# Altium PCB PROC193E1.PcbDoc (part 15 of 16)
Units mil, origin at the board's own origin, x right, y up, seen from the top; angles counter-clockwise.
Board outline 7700 x 2300 mil, 6 copper layers (Top Layer, GND 1, SIG 1, PWR, GND 2, Bottom Layer), stack 60.98 mil thick; 946 components, 667 nets, 9401 pads, 1730 vias.
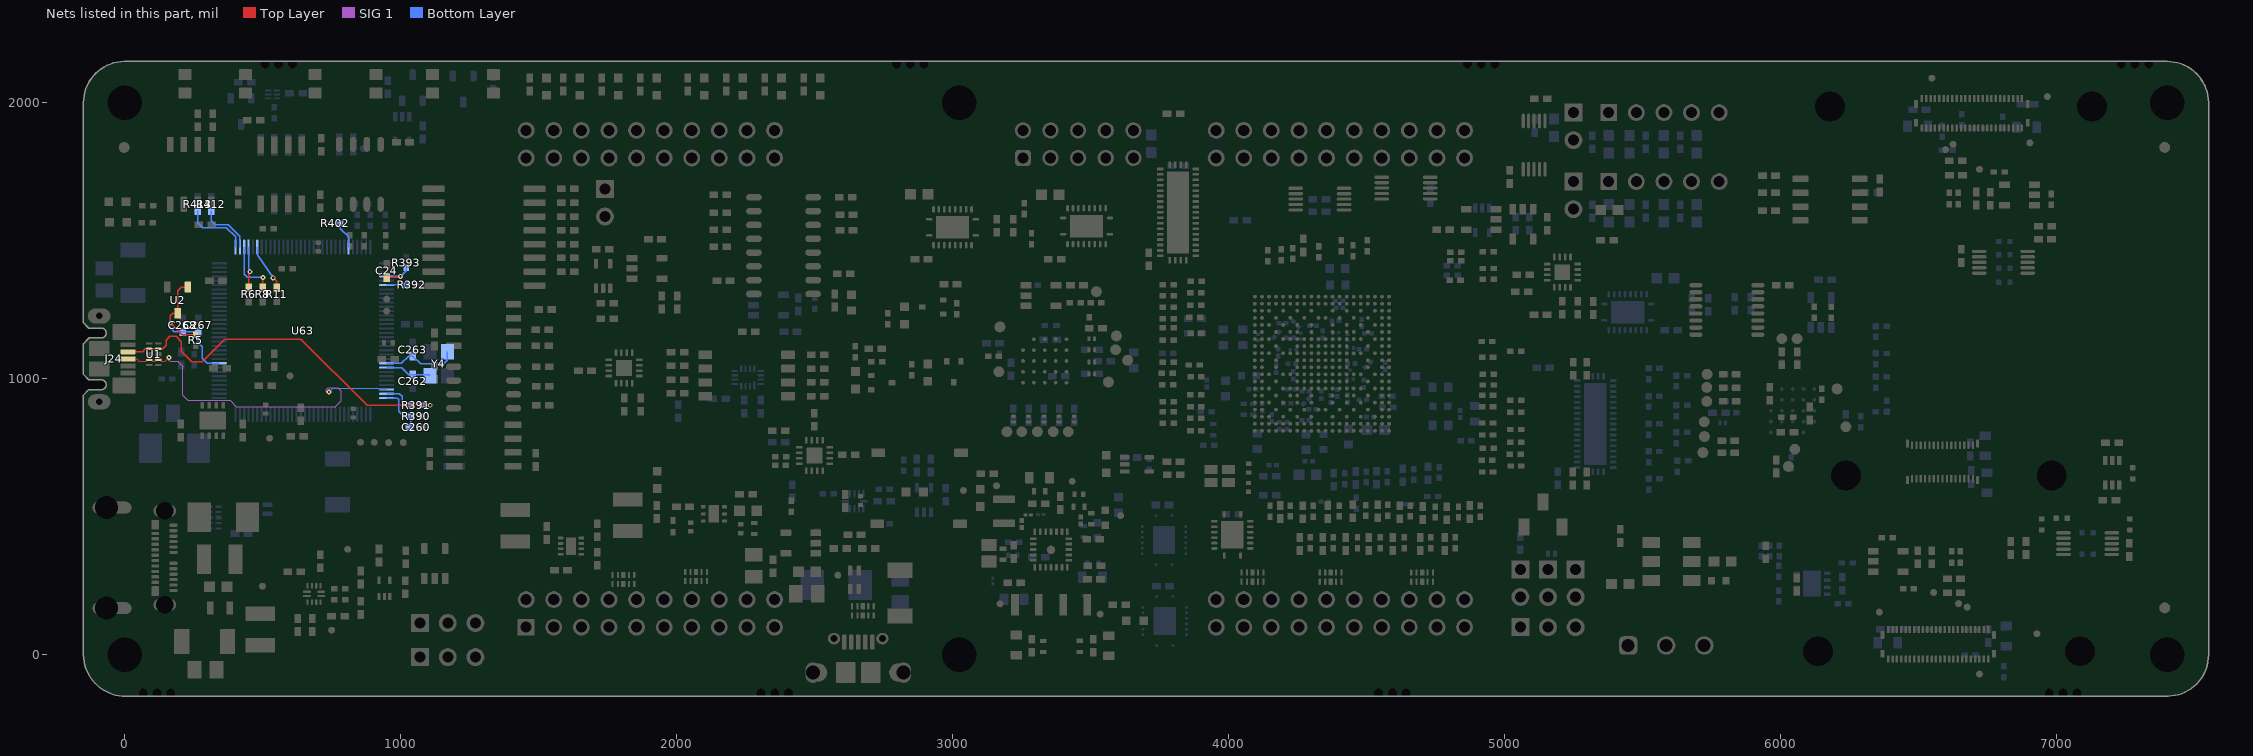
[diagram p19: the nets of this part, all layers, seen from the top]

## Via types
v1: diameter 18, hole 8, Top Layer to Bottom Layer, tented both sides, 1710 vias
v2: diameter 18, hole 8, Top Layer to Bottom Layer, tented top, 12 vias
v3: diameter 23.62, hole 11.81, Top Layer to Bottom Layer, tented both sides, 8 vias

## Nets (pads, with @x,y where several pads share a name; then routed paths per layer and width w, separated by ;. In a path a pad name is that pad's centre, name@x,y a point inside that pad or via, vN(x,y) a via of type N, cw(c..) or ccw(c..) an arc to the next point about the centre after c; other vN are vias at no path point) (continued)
XDSET_1_D_P: J24.3 U1.2 U1.9 U63.94 | length 1271.6
  Top Layer w4.2: J24.3@11.81,1072.19 42.99,1072.19 51.19,1063.99 76.14,1063.99 81.38,1069.23 U1.9@88.56,1069.23 95.75,1069.23 100.99,1063.99 109.01,1063.99 114.25,1069.23 U1.2@121.44,1069.23 128.62,1069.23 128.62,1068.29 132.92,1063.99 146.6,1063.99 v1(160,1077.39)
  SIG 1 w4: v1(160,1077.39) 160,1068.11 165,1063.11 192.24,1063.11 209.9,1045.45 209.9,940.01 228.42,921.48 381.95,921.48 404.66,898.78 762.96,898.78 785,920.82 785,954.8 772.28,967.52 736.99,967.52 729.55,960.08 729.55,955.61 733.52,951.65 v1(740,951.65)
  Bottom Layer w4.2: v1(740,951.65) 753.4,965.05 917.83,965.05 921.1,961.77 U63.94@948.65,961.77
XDSET_1_ID: J24.4 R391.1 U1.4 U1.7 | length 1351.3
  Top Layer w5.3: J24.4@11.81,1097.78 64.17,1097.78 75,1108.6 U1.7@88.56,1108.6 U1.4@121.44,1108.6 136.73,1108.6 149.79,1121.67 149.79,1140.24 163.21,1153.65 185.77,1153.65 205.14,1134.28 205.14,1099.59 243.04,1061.69 280.18,1061.69 362.27,1143.79 638.14,1143.79 877.71,904.21 v1(1106.33,904.21)
  Bottom Layer w5.3: R391.1@1075.19,904.21 v1(1106.33,904.21)
XDSET_1_ID_R: R391.2 U63.95 | length 117.4
  Bottom Layer w5.3: U63.95@948.65,946.02 995.21,946.02 1005,936.23 1005,914.12 1014.91,904.21 R391.2@1035.82,904.21
XDSET_NRST: R392.1 U63.70 | length 72.4
  Bottom Layer w5.3: U63.70@948.65,1339.72 949.32,1340.39 R392.1@1020.82,1340.39
XDSET_OSC0: C263.2 U63.88 Y4.1 | length 278.7
  Bottom Layer w5.3: U63.88@948.65,1056.26 1001.79,1056.26 1028.04,1082.51 C263.2@1042.72,1082.51 1071.4,1053.83 1155.21,1053.83 1168.63,1067.24 Y4.1@1168.63,1097.63
XDSET_OSC1: C262.2 U63.89 Y4.3 | length 169.2
  Bottom Layer w5.3: U63.89@948.65,1040.51 1002.75,1040.51 1028.31,1014.95 C262.2@1042.72,1014.95 1101.7,1014.95 Y4.3@1105.64,1011.01
XDSET_RBIAS: R402.2 U63.59 | length 98.3
  Bottom Layer w5.3: R402.2@781.47,1563.62 781.47,1543.52 810.85,1514.13 U63.59@810.85,1477.52
XDSET_TCK: R8.2 U63.35 | length 209.9
  Top Layer w5.3: R8.2@500,1329.36 500,1366.5 v1(500.77,1367.28)
  Bottom Layer w5.3: U63.35@432.9,1477.52 432.9,1378.38 444,1367.28 v1(500.77,1367.28)
XDSET_TDI: R11.2 U63.38 | length 170
  Top Layer w5.3: v1(537.79,1365.91) 549.89,1353.81 R11.2@549.89,1329.99
  Bottom Layer w5.3: U63.38@480.15,1477.52 480.15,1453.9 481.91,1448.1 v1(537.79,1365.91)
XDSET_TMS: R6.2 U63.36 | length 152.5
  Top Layer w5.3: R6.2@448.79,1329.36 448.79,1379.32 453.93,1384.46 v1(453.93,1387.9)
  Bottom Layer w5.3: U63.36@448.65,1477.52 448.65,1396.62 453.93,1391.34 v1(453.93,1387.9)
XDSET_UARTA_RX: R413.2 U63.33 | length 238.9
  Bottom Layer w5.3: R413.2@264.01,1609.62 264.01,1566.16 283.33,1546.84 368.48,1546.84 401.41,1513.91 U63.33@401.41,1477.52
XDSET_UARTA_TX: R412.2 U63.34 | length 202.3
  Bottom Layer w5.3: R412.2@314.01,1609.62 314.01,1572.04 327.4,1558.65 374.37,1558.65 417.15,1515.86 U63.34@417.15,1477.52
XDSET_VBAT: C24.1 R393.1 U63.68 | length 141.4
  Top Layer w5.3: C24.1@948.65,1367.28 995.1,1367.28 v1(999.04,1371.22)
  Bottom Layer w5.3: U63.68@948.65,1371.22 v1(999.04,1371.22) 1020,1392.18 R393.1@1020,1401.56
XDSET_VREFA: C267.2 C268.2 R5.1 U2.1 U2.3 U63.9 | length 587.1
  Top Layer w5.3: U2.1@228.9,1332 203.89,1332 191.5,1319.61 U2.3@191.5,1237.51 173.18,1237.51 165,1229.33 v1(165,1203.44) 208.88,1159.56 R5.1@257.13,1159.56
  Bottom Layer w5.3: v1(165,1203.44) 165,1185.04 179.89,1170.15 C268.2@210.82,1170.15 C267.2@265.82,1170.15 265.82,1131.18 280.11,1116.89 280.11,1075.03 298.89,1056.26 U63.9@342.35,1056.26
XDSUSB0VBUS: C260.2 R390.1 U63.96 | length 179.6
  Bottom Layer w5.3: U63.96@948.65,930.28 987.32,930.28 992.6,925 992.6,882.15 1010.53,864.22 R390.1@1035.82,864.22 C260.2@1035.82,824.22
pads on no net: 1. 2. 3. 4. 5. 7. 8. 9. 10. 11. D17.1S D17.2S Designator1. Designator2. Designator3. Designator4. Designator5. Designator6. Designator7. Designator8. Designator9. Designator10. Designator11. Designator12. Designator13. Designator14. Designator15. Designator16. Designator17. Designator18. Designator19. Designator20. Designator21. Designator22. FID1.1 FID1_1.1 FID1_1_1.1 FID1_1_2.1 FID1_1_3.1 FID2.1 FID3.1 FID4.1 FID4_1.1 FID4_1_1.1 FID4_1_2.1 FID4_1_3.1 FID5.1 FID6.1 J22.24 J22.25 J22.26 J22.27 J22.28 J22.29 J22.30 J25.A2 J25.A3 J25.A8 J25.A10 J25.A11 J25.B2 J25.B3 J25.B8 J25.B10 J25.B11 LBL1.0 SH-J1.0 SH-J2.0 SH-J3.0 SH-J4.0 SH-J5.0 SH-J6.0 SH-J7.0 SH-J8.0 U1.3@121.44,1088.92 U1.5 U1.6 U1.8@88.56,1088.92 U4.7 U4.9@293.89,848.32 U4.9@343.49,848.32 U14.0 U15.1 U16.7 U16.8 U16.9 U16.10 U16.17@1809.13,1039.54 U17.3@1806.54,256.9 U17.8@1806.54,289.78 U19.3@2069.81,267.45 U19.8@2069.81,300.32 U20.5 U20.7@2134.1,492.72 U20.7@2134.1,528.15 U23.17@2498.69,722.15 U24.3@2674,142.95 U24.5 U24.6 U24.8@2674,175.83 U26.A2 U26.A3 U26.B1 U26.B5 U26.C5 U29.6 U29.15 U31.16 U31.18 U31.19 U33.3@4085.92,264.9 U33.8@4085.92,297.78 U34.U17 U36.3@4369.09,297.78 U36.8@4369.09,264.9 U38.3@4700.31,297.78 U38.8@4700.31,264.9 U42.17@5208.52,1386.21 U43.3 U43.12 U43.13 U43.14 U51.A2 U51.A3 U51.B1 U51.B5 U51.C5 U55.1 U56.12 U56.13 U56.14 U59.6 U59.12 U62.1 U63.2 U63.5 U63.6 U63.11 U63.12 U63.13 U63.14 U63.15 U63.18 U63.19 U63.20 U63.21 U63.22 U63.23 U63.24 U63.25 U63.27 U63.29 U63.30 U63.31 U63.32 U63.40 U63.41 U63.44 U63.45 U63.46 U63.53 U63.54 U63.56 U63.57 U63.65 U63.67 U63.83 U63.84 U63.85 U63.86 U63.91 U63.92 U63.102 U63.103 U63.104 U63.105 U63.106 U63.107 U63.108 U63.109 U63.110 U63.111 U63.112 U63.116 U63.117 U63.118 U63.119 U63.120 U63.121 U63.123 U63.124 U63.125 U63.126 U63.127 U63.128 U65.3@306.02,497.27 U65.8@338.89,497.27

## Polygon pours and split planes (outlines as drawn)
GND on Top Layer "NONET_L-01_P-001" (solid, remove dead copper, pour order 435): -15.19,2149.23 7451.59,2149.23 7550,2050.82 7550,-68.99 7468.99,-150 -18.42,-150 -148.4,-20.02 -148.4,2018.56 -18.05,2148.91
GND on Top Layer "GND 1-GND" (solid, remove dead copper, pour order 434): 231.17,592.07 212.36,573.26 212.36,509.24 191.6,488.49 25,488.49 25,221.51 213.11,221.51 307.01,127.6 307.01,-150 7550,-150 7550,2149.99 -150,2150.53 -150,1778.42 1334.22,1778.42 1334.22,592.07
GND_XDS on Top Layer "SIG 1-VDD_XDS3V3" (solid, pour order 410): 40.11,861.16 41,862.05 41,1114.67 96.18,1169.86 96.18,1372.55 -120,1372.55 -120,1699.76 1266.69,1699.76 1266.69,668.8 -130.32,668.8 -130.32,860.97 -130.12,861.16
SHIELD5 on Top Layer "NONET_L-01_P-001" (solid, pour order 355): 2974.79,224.27 2974.79,142.62 2878.87,46.69 2878.87,-123.83 2443.02,-123.83 2443.02,69.26 2458.87,85.11 2586.46,85.11 2586.46,12.74 2591.36,7.84 2718.57,7.84 2721.98,11.25 2721.98,72.03 2735.44,85.49 2735.44,224.27
GND on Top Layer "NONET_L08_P-001" (solid, remove dead copper, pour order 383): 3360.88,304.77 3351.02,304.77 3351.02,306.75 3310.53,347.24 3310.53,425.68 3351.02,466.17 3351.02,485.55 3336.99,499.58 3320.62,515.95 3320.62,674.03 3401.46,674.03 3401.46,555.87 3372.67,555.87 3360.88,544.08 3360.88,435 3370.91,424.96 3383.48,424.96 3390.54,432.02 3390.54,461.18 3449.59,520.23 3449.59,585.56 3466.16,602.13 3564.98,602.13 3579.55,587.55 3579.55,504.92 3566.61,491.98 3435.37,491.98 3401.46,458.06 3401.46,347.32 3360.88,306.75
VSYS_3V3 on Top Layer "TOP_LAYER_VSYS_3V3_P415" (solid, pour order 415): 6777.38,170.53 6777.78,170.92 6777.78,228.15 6723.17,228.15 6712.58,217.56 6712.58,78.37 6713.15,77.8 6751.18,77.23 6777.38,103.43 6777.38,155.63
VSYS_3V3 on Top Layer "NONET_L08_P-001" (solid, remove dead copper, pour order 361): 3443.33,334.07 3469.19,359.93 3505.14,359.93 3505.14,306.43 3500.08,301.36 3413.94,301.36 3410.09,305.22 3410.09,334.07
VSYS_5V0 on Top Layer "NONET_L08_P-001" (solid, remove dead copper, pour order 357): 3303.01,406.57 3273.54,406.57 3263.98,416.13 3166.55,416.13 3099.42,483.25 3055.53,483.25 3055.53,373.17 3233.69,373.17 3240.12,379.6 3254.86,394.34 3303.01,394.34
VUSB_5V0 on Top Layer "Top Layer-VUSB_5V0" (solid, pour order 286): 1222.91,293.21 1222.91,441.28 1589.79,441.28 1589.79,395.68 1561.88,395.68 1534.79,368.6 1534.79,293.21
VSYS_5V0 on Top Layer "NONET_L-01_P-001" (solid, pour order 271): 3216.24,283.34 3227.54,272.05 3227.54,262.84 3227.56,242.34 3276.33,242.34 3322,288.02 3322,326.74 3320.35,328.39 3312.81,328.39 3311.66,327.24 3311.66,306.09 3303.9,298.33 3293.98,298.33 3265.58,326.74 3199.85,326.74 3199.85,283.34
VSYS_3V3 on Top Layer "NONET_L-01_P-001" (solid, remove dead copper, pour order 382): 6547.24,1840.53 6547.24,1921.27 6546.1,1922.41 6523.58,1922.41 6522.44,1921.27 6522.44,1895.04 6514.04,1886.64 6514.04,1840.53
VSYS_5V0 on Top Layer "Top Layer-VSYS_5V0" (solid, pour order 350): 1904.7,511.4 1874.86,481.55 1777.18,481.55 1747.34,451.71 1642.72,451.71 1642.72,395.68 1743.97,395.68 1743.97,319.66 1966.6,319.66 1966.6,453.86 1979.3,466.55 2106.02,466.55 2106.02,497.17 2085.46,497.17 2071.24,511.4
VBUS_TYPEC_5V0 on Top Layer "Top Layer-VBUS_TYPEC_5V0" (solid, pour order 274): 330.42,433.95 330.42,564.66 199.12,564.66 199.12,253 213.59,238.52 213.54,166.87 253.65,126.75 325.36,126.75 330.42,131.81
GND on Top Layer "Top Layer-GND" (solid, pour order 354): 1883.43,514.37 1874.16,505.1 1770.6,505.1 1724.71,459.22 1634.79,459.22 1634.79,372.77 1669.79,372.77 1669.79,354.78 1685.28,339.3 1724.79,339.3 1724.79,287.77 1589.79,287.77 1589.79,324.3 1599.79,334.3 1599.79,459.22 1361.18,459.22 1361.18,594.62 1768.56,594.62 1883.43,594.62
SHIELD4 on Top Layer "NONET_L-01_P-001" (solid, pour order 356): -150,1347.16 75,1347.16 75,1178.55 38.89,1142.44 -26.22,1142.44 -26.22,1004.94 40.11,1004.94 40.11,880 -150,880
SHIELD1 on Top Layer "NONET_L-01_P-001" (solid, remove dead copper, pour order 344): 204.58,204.45 204.58,139.03 248.69,94.92 248.88,13.13 276.57,-14.56 276.57,-95.31 269.23,-102.65 159.12,-102.65 146.06,-89.59 146.06,79.04 95.56,129.54 -104.42,129.54 -130.04,155.17 -130.67,155.17 -130.67,564.66 -111.46,583.87 183.67,583.87 188.47,579.07 188.47,511.64 175.76,498.93 125.63,498.93 115.91,508.66 30.41,508.66 7,485.24 7,203.26 128.97,204.45
VCORE_1V2 on Top Layer "NONET_L08_P-001" (solid, remove dead copper, pour order 359): 3285.75,114.81 3396,114.81 3396,40 3147.09,40 3147.09,224.24 3262.4,224.24 3262.4,138.17
VSYS_2V5 on Top Layer "NONET_L08_P-001" (solid, remove dead copper, pour order 360): 3461.57,135.66 3461.57,123.57 3452.94,114.94 3420,114.94 3420,40.67 3601.92,40.67 3601.92,221.26 3461.57,221.26
VSYS_2V5 on Top Layer "NONET_L-01_P-001" (solid, remove dead copper, pour order 407): 6836.98,1840.08 6836.98,1920.82 6838.12,1921.96 6860.64,1921.96 6861.78,1920.82 6861.78,1894.58 6870.18,1886.18 6870.18,1840.08
VSYS_1V8 on Top Layer "NONET_L08_P-001" (solid, remove dead copper, pour order 362): 3409.69,434.03 3409.88,433.84 3428.93,433.84 3447.12,452.03 3628.99,452.03 3628.99,483.71 3537.17,483.71 3436.32,483.71 3409.69,457.08
VDD_1P8 on Top Layer "NONET_L08_P-001" (solid, remove dead copper, pour order 358): 3382.55,434.69 3382.55,461.52 3446.72,525.69 3446.72,598.83 3446.72,633.28 3438,642 3426,642 3413.05,629.05 3413.05,552.67 3405.9,545.52 3379.28,545.52 3370.49,536.73 3370.49,434.69
VSYS_3V3 on Top Layer "NONET_L08_P-001" (solid, remove dead copper, pour order 370): 3305.06,534.04 3305.06,677.7 3295.45,687.31 3139.63,687.31 3128.55,676.23 3128.55,539.03 3133.54,534.04
GND on Top Layer "NONET_L-01_P-001" (solid, pour order 381): 2737.36,400.46 2972.19,400.46 2972.19,247.21 2737.36,247.21
GND on Top Layer "NONET_L-01_P-001" (solid, pour order 402): 3042.19,365 3234.41,365 3234.41,307.65 3228.75,301.99 3228.75,259.44 3042.19,259.44
VUSB_5V0 on Top Layer "NONET_L-01_P-001" (solid, pour order 376): 2434.84,407.87 2201,407.87 2201,327.93 2435.46,327.93
VSYS_3V3 on Top Layer "NONET_L08_P-001" (solid, remove dead copper, pour order 363): 3409.1,425.83 3443.93,425.83 3452.72,434.62 3507.33,434.62 3507.33,385.87 3462.11,385.87 3431.99,415.99 3409.1,415.99
VSYS_2V5 on Top Layer "NONET_L-01_P-001" (solid, remove dead copper, pour order 412): 6424.98,160.27 6424.98,79.53 6423.84,78.39 6401.31,78.39 6400.17,79.53 6400.17,105.77 6391.77,114.16 6391.77,160.27
VSYS_5V0 on Top Layer "NONET_L-01_P-001" (solid, pour order 270): 3503.5,285.66 3420.67,285.66 3400.24,306.09 3400.24,327.24 3399.09,328.39 3391.55,328.39 3389.9,326.74 3389.9,291.72 3441.59,240.03 3503.45,240.03
VUSB_5V0 on Top Layer "NONET_L-01_P-001" (solid, remove dead copper, pour order 317): 360.64,202.13 419.78,202.13 483.11,265.47 603.35,265.47 603.35,114.94 367.41,114.94 360.42,121.94 360.42,170.11
GND on Top Layer "NONET_L-01_P-001" (solid, remove dead copper, pour order 285): 350.16,564.66 524.47,564.66 524.47,339.54 413.08,228.15 350.16,228.15
GND on Top Layer "NONET_L-01_P-001" (solid, remove dead copper, pour order 343): 339.21,95.67 548.79,95.67 560.55,83.91 560.55,-78.61 543.98,-95.17 312.39,-95.17 305.53,-88.32 305.53,62
NetL4_1 on Top Layer "NONET_L08_P-001" (solid, remove dead copper, pour order 268): 3352.17,293.77 3341.4,304.55 3331.35,304.55 3331.35,284.45 3283.35,236.46 3283.35,142.27 3352.17,142.27
NetL5_1 on Top Layer "NONET_L08_P-001" (solid, remove dead copper, pour order 267): 3370.51,304.57 3364.2,298.26 3364.2,142.27 3436.32,142.27 3436.32,230.05 3380.56,285.82 3380.56,304.57
NetC65_2 on Top Layer "NONET_L08_P-001" (solid, remove dead copper, pour order 365): 3262.84,469.73 3280.06,452.51 3280.06,430.86 3285.09,425.83 3302.8,425.83 3302.8,415.99 3276.58,415.99 3259.96,432.62 3175.19,432.62 3136.36,471.45 3136.36,496.42 3229.84,496.42 3229.84,476.69 3236.79,469.73
VBUS_MICRO_AB_5V0 on Top Layer "NONET_L-01_P-001" (solid, pour order 375): 2599.36,176.34 2612.73,162.96 2612.73,72.46 2612.57,21.32 2583.19,21.32 2583.19,70.54 2546.42,107.31 2478.13,107.31 2478.13,381.86 2599.99,381.86
VPP_AM261_1V7 on Top Layer "NONET_L-01_P-001" (solid, pour order 374): 2163.63,494.3 2359.95,494.3 2359.95,461.41 2163.63,461.41
GND_XDS on Top Layer "NONET_L-01_P-001" (solid, pour order 373): 363.98,880.8 191.02,880.8 191.02,815.84 460.46,815.84 460.46,880.73
VDD_XDS3V3 on Top Layer "NONET_L-01_P-001" (solid, remove dead copper, pour order 371): 493.95,807.07 325.23,807.07 325.23,694.84 493.95,694.84
GND on Bottom Layer "GND 1-GND" (solid, remove dead copper, pour order 446): 231.17,592.07 212.36,573.26 212.36,509.24 191.6,488.49 27.5,488.49 27.5,221.51 213.11,221.51 307.01,127.6 307.01,-150 7550,-150 7550,2149.99 -150,2150.53 -150,1778.42 1334.22,1778.42 1334.22,592.07
VSYS_2V5 on Bottom Layer "NONET_L-01_P-001" (solid, pour order 445): 3405,45 3374,14 3309,14 3298,3 3298,-126 4621.54,-126 4630.42,-117.11 4630.42,-25.42 4613,-8 4332,-8 4274,-66 3786,-66 3774.56,-77.44 3525.44,-77.44 3505,-57 3505,64 3457,112 3405,112
VSYS_5V0 on Bottom Layer "NONET_L08_P-001" (solid, remove dead copper, pour order 379): 3274.96,317.35 3293.98,298.33 3342.09,298.33 3356.56,283.86 3356.56,222.4 3311.51,177.36 3227.36,177.36 3227.36,272.02 3216.04,283.34 3202.39,283.34 3202.39,317.35
VREG on Bottom Layer "NONET_L-01_P-001" (solid, remove dead copper, pour order 340): 3228.17,337.25 3223.85,341.57 3223.85,378.46 3240.34,394.95 3240.34,467 3303.72,467 3303.72,337.25
VCORE_1V2 on Bottom Layer "NONET_L-01_P-001" (solid, remove dead copper, pour order 449): 4201.03,1012.08 4201.03,948.61 4202.78,946.86 4223.83,946.86 4226.4,949.43 4226.4,970.59 4246.3,990.49 4246.3,1012.3 4201.47,1012.3
VCORE_1V2 on Bottom Layer "NONET_L-01_P-001" (solid, remove dead copper, pour order 448): 4250.26,1177.64 4250.26,1159.15 4255.74,1153.67 4319.51,1153.67 4325.47,1159.63 4325.47,1175.76 4322.01,1179.22 4252.01,1179.22 4250.34,1177.56
VCORE_1V2 on Bottom Layer "NONET_L-01_P-001" (solid, remove dead copper, pour order 283): 4204.5,1132.67 4204.5,1079.59 4218.81,1065.28 4241.44,1065.28 4246.11,1069.94 4246.11,1086.26 4233.38,1098.99 4233.38,1106.08 4239.37,1112.07 4239.37,1128 4229.96,1137.4 4209.23,1137.4
VCORE_1V2 on Bottom Layer "NONET_L-01_P-001" (solid, remove dead copper, pour order 339): 4352.47,1173.02 4352.47,1153.84 4357.59,1148.72 4367.45,1148.72 4373.18,1154.46 4418.25,1154.46 4421.49,1151.22 4434.36,1151.22 4439.76,1145.82 4439.76,1048.5 4428.49,1037.24 4428.49,1028.13 4439.76,1016.86 4439.76,992.64 4436.99,989.87 4436.99,960.16 4441.72,955.43 4456.32,955.43 4461.59,960.71 4461.59,1005.01 4471.49,1014.91 4471.49,1037.34 4490.93,1056.77 4490.93,1068.04 4480.75,1078.22 4470.39,1078.22 4460.12,1088.49 4460.12,1154.06 4435.28,1178.91 4358.3,1178.91 4352.35,1172.96 4352.35,1172.91 4352.54,1172.72
VSYS_3V3 on Bottom Layer "Bottom Layer-VSYS_3V3" (solid, remove dead copper, pour order 417): 3537.43,385.22 3508.86,356.65 3508.86,317.52 3458.63,317.52 3458.63,437.67 3537.43,437.67
VSYS_5V0 on Bottom Layer "NONET_L-01_P-001" (solid, pour order 444): 4092,589 4093,588 4140.85,588 4140.85,567.15 4170,538 4369.73,538 4407.02,500.71 4756.29,500.71 4952,305 4952,79.07 4885,79.07 4885,262 4736,411 4311,411 4227,495 4092,495
GND_XDS on Bottom Layer "SIG 1-VDD_XDS3V3" (solid, pour order 422): 41,861 41,1114.67 96.18,1169.86 96.18,1372.55 -120,1372.55 -120,1699.76 1266.69,1699.76 1266.69,668.8 -120,668.8 -120,861
VSYS_3V3 on Bottom Layer "BOTTOM_LAYER_VSYS_3V3_P425" (solid, pour order 425): 6839.91,69.54 6828.8,58.43 6705.57,58.43 6696,68 6696,189 6726.33,219.33 6820.58,219.33 6839.91,199.99
VSYS_2V5 on Bottom Layer "NONET_L-01_P-001" (solid, pour order 424): 6431.04,-1.12 6427.14,-5.02 6378.44,-5.02 6378.44,158.91 6431.04,158.91
VUSB_5V0 on Bottom Layer "NONET_L-01_P-001" (solid, pour order 409): 1565.09,435 1577.09,423 2270,423 2270,230.45 1199.01,230.45 1199.01,435
SHIELD4 on Bottom Layer "Bottom Layer-SHIELD4" (solid, pour order 447): 20,1122.51 89.84,1192.35 89.84,1227.7 89.84,1344.61 -135,1344.61 -135,880 20,880
VSYS_3V3 on Bottom Layer "NONET_L-01_P-001" (solid, pour order 440): 4646.95,994.87 4816.76,994.87 4823.66,987.98 4823.66,935.5 4810.39,922.23 4776.76,922.23 4776.76,876.35 4910.93,876.35 4920.83,886.25 4920.83,1032.67 4910.26,1043.23 4667.96,1043.23 4647.15,1022.42
VSYS_5V0 on Bottom Layer "NONET_L-01_P-001" (solid, pour order 433): 3427.09,300.92 3488.08,300.92 3502.43,286.58 3502.43,230.08 3495.28,222.93 3435.24,222.93 3427.09,231.08
VSYS_2V5 on Bottom Layer "NONET_L-01_P-001" (solid, pour order 414): 6828.59,1996.34 6844.06,2011.81 6889.35,2011.81 6889.35,1836.31 6828.59,1836.31
VSYS_3V3 on Bottom Layer "BOTTOM_LAYER_VSYS_3V3_P426" (solid, pour order 426): 2913.34,590.14 2908.52,594.97 2908.52,678.21 2996.05,678.21 3000.6,673.67 3000.6,601.86 2986.58,587.84 2985.67,588.75 2913.92,588.75
GND on Bottom Layer "NONET_L-01_P-001" (solid, pour order 401): 2689.85,400.46 2621.69,332.3 2621.69,199.26 2706.25,199.26 2754.43,247.21 2972.19,247.21 2972.19,400.46
VSYS_1V8 on Bottom Layer "NONET_L-01_P-001" (solid, pour order 438): 7050.59,745.88 7092.49,703.98 7092.49,546.74 7106.79,532.44 7147.02,532.44 7152.64,538.06 7152.64,805.69 7115.02,843.32 6678.87,843.32 6660.12,824.57 6660.12,745.88
VSYS_1V8 on Bottom Layer "NONET_L-01_P-001" (solid, pour order 436): 3542.05,545.83 3639.07,545.83 3639.07,447.45 3542.05,447.45
VCORE_1V2 on Bottom Layer "NONET_L-01_P-001" (solid, pour order 430): 3947.79,1141.37 4078.21,1141.37 4082.01,1145.17 4167.87,1145.17 4167.87,1117.8 4166.69,1116.61 4130.24,1116.61 4114.23,1100.6 4021.1,1100.6 3984.5,1064 3947.79,1064
VSYS_3V3 on Bottom Layer "NONET_L-01_P-001" (solid, pour order 406): 6562.41,1994.34 6509.8,1994.34 6509.8,1814.96 6562.41,1814.96
GND on Bottom Layer "NONET_L08_P-001" (solid, remove dead copper, pour order 369): 3350.31,1194.83 3311.74,1194.83 3308.94,1192.02 3308.94,1110.51 3313.42,1106.03 3344.51,1106.03 3350.31,1111.82
VSYS_5V0 on Bottom Layer "NONET_L08_P-001" (solid, remove dead copper, pour order 377): 3214.31,374.49 3055.53,374.49 3055.53,483.67 3193.69,483.68 3214.31,463.06
VSYS_1V8 on Bottom Layer "NONET_L08_P-001" (solid, remove dead copper, pour order 353): 3403.27,1203.09 3360.26,1203.09 3360.26,1112.67 3365.85,1107.08 3398,1107.08 3403.27,1112.35
GND on Bottom Layer "NONET_L-01_P-001" (solid, remove dead copper, pour order 403): 2245.19,1048.46 2268.81,1048.46 2268.81,1024.84 2274.39,1019.26 2274.39,994.49 2259.7,994.49 2245.19,1009
SHIELD5 on Bottom Layer "NONET_L-01_P-001" (solid, pour order 372): 2974.79,224.27 2974.79,142.62 2878.87,46.69 2878.87,-123.83 2443.02,-123.83 2443.02,69.26 2458.87,85.11 2586.46,85.11 2586.46,12.92 2590.98,8.4 2719.13,8.4 2721.98,11.25 2721.98,72.03 2735.44,85.49 2735.44,224.27
VBUS_MICRO_AB_5V0 on Bottom Layer "NONET_L-01_P-001" (solid, pour order 423): 2443.02,332.24 2567.65,332.24 2567.65,103.2 2443.02,103.2
VCORE_1V2 on Bottom Layer "NONET_L-01_P-001" (solid, pour order 427): 4400.64,1248.37 4400.64,1225.39 4422.62,1225.39 4422.62,1248.37 4455.9,1281.65 4455.9,1426.27 4394.49,1426.27 4394.49,1316.44 4400.64,1310.29
VCORE_1V2 on Bottom Layer "NONET_L-01_P-001" (solid, pour order 432): 4202.86,873.33 4233.77,873.33 4233.77,813 4221.06,800.29 4202.86,800.29
SHIELD1 on Bottom Layer "NONET_L-01_P-001" (solid, remove dead copper, pour order 351): 7,485.24 30.41,508.74 185.57,508.74 188.47,511.64 188.47,579.07 183.67,583.87 -111.46,583.87 -130.67,564.66 -130.67,155.17 -130.04,155.17 -104.42,129.54 95.56,129.54 146.06,79.04 146.06,-89.59 159.12,-102.65 249,-102.65 249,94.61 204.58,139.03 204.58,183.4 183.53,204.45 7,204.45
VBUS_XDS_5V0 on Bottom Layer "NONET_L-01_P-001" (solid, remove dead copper, pour order 345): 51.41,869.79 11.81,830.19 11.81,669.95 135.59,669.95 135.59,948.23 145.89,958.54 145.89,1020.83 136.02,1030.7 51.52,1030.7
GND_XDS on Bottom Layer "NONET_L-01_P-001" (solid, pour order 387): 150,839.02 164.43,824.6 164.43,669.95 342.74,669.95 342.74,824.42 259.98,907.19 259.98,997.94 252.52,1005.4 210.68,1005.4 150,944.72
VSYS_5V0_BP_2 on PWR "NONET_L-01_P-001" (solid, pour order 429): 3286.59,196.41 3249.85,233.15 3139.57,231.87 3040.78,330.66 1404.8,330.66 1331.55,255.94 1254.94,255.94 1134.47,135.47 1134.47,-98.98 1261.02,-98.98 1513.8,153.8 3099.94,153.8 3163.42,90.33 3163.42,-91.37 3683.42,-91.37 3905.3,130.51 3996.49,130.51 3996.49,241.8 3665.72,241.8 3439.51,19 3302.81,19 3286.59,35.21
VSYS_5V0 on PWR "NONET_L-01_P-001" (solid, pour order 390): 3163.33,501 3271,501 3283.96,488.04 3283.96,247.31 3126.46,247.31 3020.12,353.65 1735.09,353.65 1724.52,364.22 1724.52,711.03 2368.09,711.03 2384.89,727.83 2384.89,841.34 2396.77,853.22 2418,853.22 2560.19,711.03 2953.3,711.03
VSYS_1V8 on PWR "NONET_L-01_P-001" (solid, pour order 392): 3042.44,1417.88 3350.12,1417.88 3507.11,1417.88 3759.92,1670.69 3871.2,1669.25 4487.05,1669.25 4652.82,1668.99 4988,1333.81 4988,1018.79 5271.32,735.47 5448.51,735.47 5516.9,803.86 5516.9,1127.04 5581.85,1191.98 6679.02,1191.98 6776,1095 6776,565.73 6701.56,491.29 5034.89,491.29 4960,416.4 4960,259.57 3711.5,259.57 3564.6,406.46 3564.1,595.14 4059.26,1090.3 4208.39,1090.3 4212.28,1086.4 4212.28,1023.5 4042.04,853.26 4042.04,603.89 4073.93,572 4751,572 4778,599 4778,817 4721,874 4540.67,874 4480.03,934.64 4469.94,944.73 4469.9,952.65 4593.5,1076.24 4593.5,1361.28 4494.28,1460.5 3890.61,1460.5 3469.78,1039.66 3328.15,898.04 2931.07,898.04 2791.31,898.04 2791.31,1318.99 2890.08,1417.88
VCORE_1V2 on PWR "NONET_L-01_P-001" (solid, pour order 299): 3592.24,212.54 3592.24,330.08 3539.83,382.75 3539.83,599.85 4054.92,1114.94 4195.48,1114.94 4221.71,1088.72 4221.71,1020.44 4202.86,1001.59 4202.86,963.84 4223.07,943.63 4223.07,891.44 4206.57,874.94 4206.57,837.4 4288.2,837.4 4288.2,944.44 4312.65,968.89 4453.01,968.89 4575.75,1091.63 4575.75,1341.55 4481.21,1438 3891.02,1438 3302.23,849.2 3302.23,545.17 3259.07,502.17 3259.07,359.81 3302.23,316.65 3302.23,38 3417.7,38
VSYS_3V3 on PWR "NONET_L-01_P-001" (solid, pour order 397): 2771,1334 2771,907 2796.87,881.13 3204.48,881.13 3287.13,798.48 3287.13,547.64 3272.64,533.15 3184.25,533.15 2986.21,731.19 2566.54,731.19 2416.59,881.13 2335.65,881.13 2262.67,957.16 2123.35,957.16 2058.98,892.78 1976.24,892.78 1921.76,947.26 1921.76,1076.7 1617.56,1076.7 1567.18,1026.33 1567.18,663.04 1475.75,663.04 1475.75,1203.33 1571,1298.58 1921.76,1298.58 1977.66,1355.28 1977.66,1557.34 1952,1583 1773.73,1583 1683.22,1673.51 1683.22,1886.71 1670.74,1899.2 1018.14,1899.2 928.08,1989.26 444.34,1989.26 325.82,1870.74 278.09,1870.74 278.09,2124.51 6415.72,2124.51 6759.81,2124.51 6800.32,2084 6800.32,1841.44 6924.76,1717 7076,1717 7309.47,1483.53 7309.47,399.03 7104.07,193.63 5448.51,193.63 5305.46,50.59 4997.94,50.59 4997.94,417.02 5037.25,456.33 6717.33,456.33 6800.32,539.32 6800.32,1131.44 6715.18,1214 5545.48,1214 5494.7,1163.22 5494.7,843.2 5431.96,780.45 5271.09,780.45 5017.8,1033.74 5017.8,1313.74 4662.71,1668.83 3708.06,1668.83 3491.87,1452.64 2889.64,1452.64
VSYS_2V5 on PWR "NONET_L-01_P-001" (solid, pour order 416): 6826.17,1850.36 6927.53,1749 6955.59,1749 7085,1749 7337,1497 7337,357.41 7147.59,168 5461.34,168 5315.45,22.11 4508.56,22.11 4508.56,-124.5 7260.29,-124.5 7524.51,139.72 7524.51,1951.47 7376.22,2099.76 6826.17,2099.76
VDDA_AM261_1V8_LDO on PWR "NONET_L-01_P-001" (solid, pour order 279): 4327.84,878.93 4327.84,857.55 4308.59,838.15 4283.71,813.27 4195.28,813.27 4183.43,828.4 4183.43,882.13 4205.1,902.88 4205.1,932.83 4196.65,941.28 4159.32,941.28 4063.25,845.21 4063.25,599.35 4073.75,588.85 4381.33,588.85 4381.33,852.79 4368.1,866.02 4368.1,878.93
SHIELD4 on PWR "Bottom Layer-SHIELD4" (solid, pour order 303): 20,1122.51 75,1177.51 75,1344.61 -135,1344.61 -135,880 20,880
VSYS_TA_3V3 on PWR "NONET_L-01_P-001" (solid, pour order 396): 2354.59,859.55 2354.59,715.75 1689.96,715.75 1689.96,519.73 1651.3,481.07 1387.06,481.07 1343.51,524.62 1343.51,1744.08 1309.16,1778.42 442.89,1778.42 442.89,1969.88 919.31,1969.88 1004.83,1884.36 1625.69,1884.36 1655.69,1854.37 1655.69,1605.38 1700.61,1560.46 1937.95,1560.46 1954.9,1543.52 1954.9,1366.9 1904,1316 1563,1316 1455.36,1208.36 1455.36,629.87 1587.23,629.87 1587.23,1032.45 1611.68,1056.9 1896.45,1056.9 1896.45,1053.66 1910.45,1039.66 1908.31,1037.53 1908.31,928.3 1964.74,871.87 2074.65,871.87 2139.66,936.88 2252.21,936.88 2329.54,859.55
SHIELD1 on PWR "NONET_L-01_P-001" (solid, remove dead copper, pour order 346): 7,498.93 7,204.45 183.53,204.45 204.58,183.4 204.58,139.03 248.88,94.73 248.88,-102.65 159.12,-102.65 146.06,-89.59 146.06,79.04 95.56,129.54 -104.42,129.54 -130.04,155.17 -130.67,155.17 -130.67,564.66 -111.46,583.87 183.67,583.87 188.47,579.07 188.47,511.64 175.76,498.93
VUSB_5V0 on PWR "NONET_L-01_P-001" (solid, pour order 439): 667,-125 668,-126 1110.59,-126 1110.59,142.59 1246,278 1323,278 1371,326 1371,465 1334,502 406,502 356,452 356,-125
VBUS_TYPEC_5V0 on PWR "NONET_L-01_P-001" (solid, pour order 385): 129.32,440 331.48,440 331.48,147.62 214.17,147.62 214.17,228.89 196.14,246.92 130.09,246.92
VDD_XDS3V3 on PWR "SIG 1-VDD_XDS3V3" (solid, remove dead copper, pour order 378): 41,860 41,1114.67 96.7,1169.86 96.7,1373 -150,1373 -150,1707.47 1260,1707.47 1260,664.04 -150,664.04 -150,860
VDDA_AM261_3V3 on PWR "NONET_L-01_P-001" (solid, pour order 391): 4765,810.03 4712.47,862.57 4534.22,862.57 4482.85,913.94 4472.45,913.94 4437.34,949.05 4308.44,949.05 4308.44,902.72 4365.28,902.72 4536,732 4765,732
SHIELD5 on PWR "NONET_L-01_P-001" (solid, pour order 384): 2586.46,85.11 2458.87,85.11 2443.02,69.26 2443.02,-123.83 2878.87,-123.83 2878.87,66.28 2848.8,96.35 2746.3,96.35 2721.98,72.03 2721.98,11.25 2718.65,7.92 2591.28,7.92 2586.46,12.74
GND on GND 1 "GND 1-GND" (solid, remove dead copper, pour order 347): 231.17,592.07 212.36,573.26 212.36,509.24 191.6,488.49 27.5,488.49 27.5,221.51 213.11,221.51 307.01,127.6 307.01,-150 7550,-150 7550,2149.99 -150,2150.53 -150,1778.42 1334.22,1778.42 1334.22,592.07
SHIELD5 on GND 1 "s" (solid, pour order 316): 2455.74,-123.83 2455.74,50.51 2488.43,85.11 2586.46,85.11 2586.46,12.74 2591.36,7.84 2718.57,7.84 2721.98,11.25 2721.98,72.03 2746.3,96.35 2848.8,96.35 2878.87,66.28 2878.87,-123.83
GND_XDS on GND 1 "SIG 1-VDD_XDS3V3" (solid, pour order 150): 41,862 41,1114.67 96.18,1169.86 96.18,1372.54 -120,1372.55 -120,1699.76 1266.69,1699.76 1266.69,668.81 -120,668.8 -120,862
SHIELD1 on GND 1 "NONET_L-01_P-001" (solid, remove dead copper, pour order 235): 7,498.93 7,204.45 183.53,204.45 204.58,183.4 204.58,139.03 248.88,94.73 248.88,-102.65 159.12,-102.65 146.06,-89.59 146.06,79.04 95.56,129.54 -104.42,129.54 -130.04,155.17 -130.67,155.17 -130.67,564.66 -111.46,583.87 183.67,583.87 188.47,579.07 188.47,511.64 175.76,498.93
SHIELD4 on GND 1 "Bottom Layer-SHIELD4" (solid, pour order 275): -135,1200.14 -135,1188.09 -130.32,1183.41 -79.03,1183.41 -67.34,1171.71 -67.34,1165.67 -85.04,1147.97 -130.32,1147.97 -130.32,996.4 -92.91,996.4 -78.88,996.4 -67.34,984.86 -67.34,973.55 -79.93,960.97 -130.32,960.97 -134.25,957.03 -134.68,879 20,879 20,1122.51 89.84,1192.35 89.84,1227.7 89.84,1344.61 -135,1344.61
GND on SIG 1 "NONET_L-01_P-001" (solid, remove dead copper, pour order 443): -10.32,2170.51 7456.45,2170.51 7554.87,2072.1 7554.87,-47.7 7473.85,-128.71 -13.55,-128.71 -143.53,1.27 -143.53,2039.85 -13.18,2170.2
VDDS_AM261_LDO_1V8 on SIG 1 "NONET_L-01_P-001" (solid, pour order 349): 4186.12,1000.29 4226.4,960.01 4226,959.61 4226,844.33 4142.67,761 4051,761 4041,771 4041,889.79 4095.24,944.04 4095.24,1253.78 4181.52,1340.06 4410.15,1340.06 4435.83,1314.37 4435.83,1228.17 4474,1190 4579.28,1190 4603.38,1165.9 4603.38,914.74 4587.82,899.18 4492.14,899.18 4484.11,907.21 4484.11,987.92 4514,1017.81 4514,1058.06 4519,1063.06 4519,1109 4503.43,1124.57 4464.64,1124.57 4392.78,1196.44 4376.15,1213.06 4330.06,1213.06 4319,1201.37 4301.49,1201.37 4273.67,1229.19 4221.79,1229.19 4154.17,1161.58 4154.17,1110.11 4186.12,1078.17
VSYS_3V3 on SIG 1 "SIG 1-VSYS_3V3" (solid, pour order 393): 4244.83,953.89 4188.62,1010.11 4188.62,1089.44 4173.41,1104.65 4173.41,1159.98 4222.45,1209.03 4270.31,1209.03 4300.11,1179.22 4331.84,1179.22 4350.92,1198.3 4362.89,1198.3 4391.29,1169.9 4391.29,1145.19 4411.61,1124.87 4460.05,1124.87 4482.19,1102.73 4505.92,1102.73 4505.92,1085.88 4492.02,1071.82 4492.02,1024.92 4463.37,996.27 4463.37,898.97 4486,876.35 4594.07,876.35 4627.25,909.52 4627.25,1162.98 4579.02,1211.21 4473.3,1211.21 4460.05,1224.46 4460.05,1340 4645.89,1340 4744,1241.89 4744,731.71 4658.66,648.6 4457.19,648.6 4391,582.41 3758.7,582.41 3514.19,337.9 3375.06,337.9 3178.19,534.76 3178.19,714.88 3233.88,770.57 3580.23,770.57 3784.96,975.3 3877.06,975.3 3877.06,832.67 3975.37,743 4196.1,743 4244.83,791.73 4244.83,903.67
VSYS_5V0 on SIG 1 "NONET_L-01_P-001" (solid, pour order 428): 3646.29,323.88 3741.17,323.88 3915.29,498 4146.81,498 4146.81,565.49 3775.18,565.49 3533.15,323.46 3353.49,323.46 3159.94,517 3048,517 3029,498 3029,409.34 3058.09,380.25 3133.94,380.25 3206.03,308.16 3285.77,228.42 3550.83,228.42
SHIELD5 on SIG 1 "NONET_L-01_P-001" (solid, pour order 437): 2459.37,-123.83 2459.37,46.79 2495.57,85.11 2586.46,85.11 2586.46,12.74 2591.36,7.84 2718.57,7.84 2721.98,11.25 2721.98,72.03 2746.3,96.35 2848.8,96.35 2878.87,66.28 2878.87,-123.83
VSYS_3V3_BP on SIG 1 "NONET_L-01_P-001" (solid, pour order 431): 3918.11,259 5233.07,259 5263,229.07 5263,78.9 5225.1,41 3942.46,41 3918.11,65.35
GND_XDS on SIG 1 "SIG 1-VDD_XDS3V3" (solid, pour order 413): 41,861 41,1114.67 96.18,1169.86 96.18,1372.55 -120,1372.55 -120,1699.76 1266.69,1699.76 1266.69,668.8 -120,668.8 -120,861
VSYS_5V0_BP_1 on SIG 1 "NONET_L-01_P-001" (solid, pour order 395): 1176.18,246.92 1123.48,194.23 1123.48,63.78 1147.26,40 1298.43,40 1408.42,150 1506.14,150 1506.14,246.92
SHIELD1 on SIG 1 "NONET_L-01_P-001" (solid, remove dead copper, pour order 277): 248.88,94.73 248.88,-102.65 159.12,-102.65 146.06,-89.59 146.06,79.04 95.56,129.54 -104.42,129.54 -130.04,155.17 -130.67,155.17 -130.67,564.66 -111.46,583.87 183.67,583.87 188.47,579.07 188.47,511.64 185.25,508.42 7,508.42 7,204.45 204.58,204.45 204.58,139.03
GND on GND 2 "GND 1-GND" (solid, remove dead copper, pour order 411): 231.17,592.07 212.36,573.26 212.36,509.24 191.6,488.49 27.5,488.49 27.5,221.51 213.11,221.51 307.01,127.6 307.01,-150 7550,-150 7550,2149.99 -150,2150.53 -150,1778.42 1334.22,1778.42 1334.22,592.07
GND_XDS on GND 2 "SIG 1-VDD_XDS3V3" (solid, pour order 442): 41,861 41,1114.67 96.18,1169.86 96.18,1372.55 -120,1372.55 -120,1699.76 1266.69,1699.76 1266.69,668.8 -120,668.8 -120,861
SHIELD4 on GND 2 "Bottom Layer-SHIELD4" (solid, pour order 441): 20,1122.51 75.45,1177.96 75.45,1344.61 -135,1344.61 -135,880 20,880
SHIELD1 on GND 2 "NONET_L-01_P-001" (solid, remove dead copper, pour order 280): 7,485.24 30.41,508.65 185.48,508.65 188.47,511.64 188.47,579.07 183.67,583.87 -111.46,583.87 -130.67,564.66 -130.67,155.17 -130.04,155.17 -104.42,129.54 95.56,129.54 146.06,79.04 146.06,-89.59 159.12,-102.65 248.88,-102.65 248.88,94.73 204.58,139.03 204.58,183.4 183.53,204.45 7,204.45
SHIELD5 on GND 2 "NONET_L-01_P-001" (solid, pour order 305): 2586.46,85.11 2458.87,85.11 2443.02,69.26 2443.02,-123.83 2878.87,-123.83 2878.87,66.28 2848.8,96.35 2746.3,96.35 2721.98,72.03 2721.98,11.25 2718.36,7.63 2591.91,7.63 2586.46,13.08

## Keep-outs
Keep-Out Layer:
  lines w60: -150,630.57 1300,630.57 1300,1740.81 -150,1740.81
  text ".Layer_Name" at 427,-1008.49 h60

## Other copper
Top Layer:
  region net NetL4_1: 3331.35,301.87 3341.57,301.87 3347.84,298.11 3347.96,275.74 3331.35,281.05
  region net NetL5_1: 3380.56,301.87 3370.33,301.87 3364.06,298.11 3363.95,275.74 3380.56,281.05
  text ".Layer_Name" at 427,-1008.49 h60
SIG 1:
  text ".Layer_Name" at 427,-1008.49 h60
PWR:
  text ".Layer_Name" at 427,-1008.49 h60
GND 1:
  text ".Layer_Name" at 427,-1008.49 h60
GND 2:
  text ".Layer_Name" at 427,-1008.49 h60
Bottom Layer:
  rectangle net SHIELD4: -125,1227.7 75.45,1344.22
  rectangle net GND_XDS: -120,1374.31 77.08,1510.17
  pour cut-out: 5939.11,204.64 5941.49,207.03 5994,207.03 6016.9,229.94 6076.79,229.94 6080.58,233.72 6080.58,299.88 6076.78,303.68 5978.16,303.68 5966.2,291.72 5900.64,291.72 5870.97,262.05 5870.97,7.14 5833.35,-30.49 5796.73,-30.82 5786.01,-20.11 5786.01,49.44 5751.29,84.17 5403.22,84.17 5380.46,61.4 5380.46,-18.92 5397.51,-35.97 5532.41,-35.97 5547.67,-51.23 5547.67,-74.25 5568.79,-95.36 5868.49,-95.36 5939.11,-24.75
  text ".Layer_Name" at 427,-1008.49 h60

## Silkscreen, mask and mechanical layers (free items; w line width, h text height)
Top Overlay:
  drawing of 201 lines, arcs and shapes, not listed
  text "EQEP0" at 5645,2027 h50
  text "FSI" at 3337.86,2006.03 h100
  text "ASSY" at 4015,2005 h108.27
  text "GND" at 1425.74,2003.31 h40 r90
  text "GND" at 3979,2000 h40 r90
  text "PORZ" at 434.45,1971.22 h50
  text "INT1" at 1218.73,1951.03 h50
  text "RESETn" at 758.63,1949.51 h50
  text "GND" at 5314,1847 h25
  text "ETHERNET CONNECTOR 1" at 6939.24,1826.78 h50
  text "EQEP1" at 5635.69,1799.55 h50
  text "J8" at 4924.2,1745.64 h25
  text "GND" at 7150.99,1698.86 h25
  text "GND" at 5208,1526 h25
  text "XDS110" at -114.82,1322.48 h50
  text "OSPI0" at 3105.21,1290.06 h25
  text "UART0" at -110.42,1284.4 h50
  text "LP-AM261" at 6329.31,1036.59 h75
  text "'.PRJ_Number''.PCB_Rev'" at 6660.44,987.92 h75
  text "SL#" at 6423.41,901.96 h108.27
  text "GND" at 3531.51,892.18 h25
  text "HIGH" at 2035.65,870.13 h25
  text "LOW" at 2395.11,866.81 h25
  text "BOOTMODE" at 2151.03,844.48 h25
  text "ERROR" at 2605,840 h25
  text "GND" at 1630.23,727.23 h25
  text "GND" at 6135.38,671.82 h25 r90
  text "1V8" at 3504.87,648.29 h25 r90
  text "USB TYPEC" at -104.5,644.92 h50
  text "5V0" at 1996.87,622.29 h25 r90
  text "PWR IN" at -100.95,597.47 h50
  text "1V2" at 2767.87,563.29 h25 r90
  text "OSPI1 EXPN HEADER" at 6365.91,562.19 h25
  text "VREF Select" at 5493.87,552.41 h30
  text "3V3" at 2994.29,547.13 h25
  text "ADC_VREF" at 5521.69,490.79 h50
  text "DAC_VREF" at 5262.75,490.12 h50
  text "5V" at 1476.13,285.32 h35 r90
  text "GND" at 2996.58,226.83 h25
  text "MCAN0" at 5633.41,187.28 h25
  text "ETHERNET CONNECTOR 0" at 6823.91,133.33 h50
  text "2V5" at 3634.53,56.58 h25
  text "GND" at 5267,-25 h25 r90
  text "3V3" at 5062,-29 h25 r90
  text "CANA_N" at 5352,-61 h25 r90
  text "CANA_P" at 5850.91,-74.86 h25 r90
  text "USB uAB" at 2250.42,-79.29 h50
  text "5V0" at 1037,-97 h25
  text "GND" at 1242,-99 h25
  text "GND" at 3395.68,-114.01 h25 r90
  text ".Layer_Name" at 427,-1008.49 h60
Bottom Overlay:
  drawing of 4489 lines, arcs and shapes, not listed
  text "Q1" at 345.85,1980.89 h25
  text "A" at 2620,1785 h25
  text "A" at 4295,1270 h25
  text "Y3" at 1182.98,1160 h25
  text "OSPI1" at 6012,1015 h25
  text "LP-AM261" at 1670,604 h30
  text "Development Kit" at 1718,549 h30
  text "www.ti.com/launchpad" at 2188,365 h30
  text "5V" at 3933.04,302.93 h40 r270
  text "5V" at 1431.69,290.69 h40 r270
  text "GND" at 1532.26,289.03 h36 r270
  text "GND" at 4032.22,286.42 h36 r270
  text "3V3" at 1428.18,-90.67 h40 r270
  text "3V3" at 3932.89,-96.57 h40 r270
  text ".Layer_Name" at 427,-1008.49 h60
Top Paste:
  text ".Layer_Name" at 427,-1008.49 h60
Bottom Paste:
  text ".Layer_Name" at 427,-1008.49 h60
Top Solder:
  circle w22: c6121.96,774.52 r11
  circle w22: c7141.22,213.38 r11
  circle w22: c7109.01,1709.87 r11
  circle w22: c1669.63,799.96 r11
  circle w22: c3384.35,-4.11 r11
  circle w22: c3101.45,243.88 r11
  circle w22: c3497.15,901.69 r11
  text ".Layer_Name" at 427,-1008.49 h60
  text ".Layer_Name" at 427,-1008.49 h60
Bottom Solder:
  region: 4260.92,1131.27 4260.92,977.87 4408.47,977.87 4408.47,1131.27
  text ".Layer_Name" at 427,-1008.49 h60
Drill Guide:
  text ".Layer_Name" at 427,-1008.49 h60
M1 Board Outline:
  lines w6: -18.84,-226.94 41.79,-226.94 ccw(c41.79,-187.57) 81.16,-187.57 ccw(c41.79,-187.57) 41.79,-148.2 ; 191.4,-226.94 cw(c191.4,-187.57) 152.03,-187.57 cw(c191.4,-187.57) 191.4,-148.2 ; 5729.19,2229 5789.82,2229 ; 7208.59,2150.26 ccw(c7208.59,2189.63) 7247.96,2189.63 ccw(c7208.59,2189.63) 7208.59,2229 ; 7208.59,4809.26 ccw(c7208.59,4848.63) 7247.96,4848.63 ccw(c7208.59,4848.63) 7208.59,4888 ; 7358.2,2150.26 cw(c7358.19,2189.63) 7318.83,2189.63 cw(c7358.19,2189.63) 7358.2,2229 7418.83,2229 ; 7358.2,4809.26 cw(c7358.19,4848.63) 7318.83,4848.63 cw(c7358.19,4848.63) 7358.2,4888 7418.83,4888 ; -150,-427.94 -150,-227.94 7550,-227.94 7550,-427.94 -150,-427.94 ; -150,2230 7550,2230 7550,2430 -150,2430 -150,2230 ; -150,4889 -150,5089 7550,5089 7550,4889 -150,4889
  lines w10: -150,1017.07 -150,1016.08 ; -150,3676.07 -150,3675.08 ; -2.06,2149.99 ccw(c0,2000) -150,1999.99 -150,1278.88 ; -2.06,4808.99 ccw(c0,4659) -150,4658.99 -150,3937.88 ; 0,-150 7400,-149.99 ; 0,2150 7400,2150 cw(c7400,2000) 7549.99,2002.06 ; 0,2509 7400,2509.01 ; 0,4809 7400,4809 cw(c7400,4659) 7549.99,4661.06 ; 4.17,-150 cw(c2.09,2.09) -150,0 -150,941.28 cw(c-130.32,941.28) -130.32,960.97 -84.25,960.97 ccw(c-84.25,977.87) -67.34,977.87 ccw(c-85.87,977.87) -85.87,996.4 -130.32,996.4 cw(c-130.32,1016.08) -150,1016.08 ; 4.17,2509 cw(c2.09,2661.09) -150,2659 -150,3600.28 cw(c-130.32,3600.28) -130.32,3619.97 -84.25,3619.97 ccw(c-84.25,3636.87) -67.34,3636.87 ccw(c-85.87,3636.87) -85.87,3655.4 -130.32,3655.4 cw(c-130.32,3675.08) -150,3675.08 ; 7402.06,-149.99 ccw(c7400,0) 7550,0.01 7550,2000 ; 7402.06,2509.01 ccw(c7400,2659) 7550,2659.01 7550,4659 ; -150,1016.08 -150,1128.29 cw(c-130.32,1128.29) -130.32,1147.97 -85.04,1147.97 ccw(c-85.04,1165.67) -67.34,1165.67 -67.34,1166.5 ccw(c-84.25,1166.5) -84.25,1183.41 -85.04,1183.41 ; -150,1278.88 -150,1203.09 ccw(c-130.32,1203.09) -130.32,1183.41 ; -150,1278.88 -150,1278.88 ; -150,3675.08 -150,3787.29 cw(c-130.32,3787.29) -130.32,3806.97 -85.04,3806.97 ccw(c-85.04,3824.67) -67.34,3824.67 -67.34,3825.5 ccw(c-84.25,3825.5) -84.25,3842.41 -85.04,3842.41 ; -150,3937.88 -150,3937.88 ; -150,3937.88 -150,3862.09 ccw(c-130.32,3862.09) -130.32,3842.41 -85.04,3842.41 ; -130.32,1183.41 -85.04,1183.41 ; -130.32,1183.41 -85.04,1183.41 ; -85.04,1183.41 ccw(c-85.04,1183.41) -85.04,1183.41 ; -85.04,3842.41 ccw(c-85.04,3842.41) -85.04,3842.41
  text ".Layer_Name" at 427,-930 h40
M2 Board Dimensions:
  rectangle: 10072.36,-371.24 10197.36,-246.24
  rectangle: 10197.36,-496.24 10572.36,-371.24
  lines w7: 10072.36,-371.24 11072.36,-371.24 ; 10197.36,-496.24 10197.36,-246.24 ; 10322.36,-496.24 10322.36,-246.24 ; 10572.36,-496.24 10572.36,-246.24 ; 10822.36,-496.24 10822.36,-246.24 ; 10072.36,-496.24 11072.36,-496.24 11072.36,-246.24 10072.36,-246.24 10072.36,-496.24
  text ".Layer_Name" at 427,-1008.49 h60
M3 3D STEP Top:
  text ".Layer_Name" at 427,-1008.49 h60
M4 3D STEP Bottom:
  text ".Layer_Name" at 427,-1008.49 h60
Assembly Top/Assembly Bottom Top:
  lines w4: 2842.18,812.55 2853.86,800.86 3158.53,800.86 ; 3226.39,775.14 3182.17,775.14 3164.36,792.95 3164.36,867.03 3189.06,891.73 3236.15,891.73 ; 3484.73,995.24 3524.1,995.24 3539.21,1010.34 3539.21,1148.43 3534.89,1152.75 3523.56,1152.75 ; 3503.61,967.73 3503.61,988.22 ; 3583.67,460.46 3614.84,460.46 3623.4,469.01 ; 4376.49,340.77 4376.49,359.44 ; 4628.71,334.32 4628.71,343.42 4635.33,350.04 4635.33,364.1 ; 4732,346.02 4732,363.43
  lines w10: -442,-1080.17 6158,-1080.17 ; -442,-876.83 6160,-876.83 ; -442,-673.5 -442,-1283.5 3563,-1283.5 6160,-1283.5 6160,-673.5 -441.5,-673.5 -441.5,-1283.5 1134,-1283.5 ; 2023,-1283.5 2023,-673.5 ; 3290,-876.83 3290,-673.5 ; 4130,-876.83 4130,-673.5 ; 4752,-1290 4752,-1087.17
  text "COMPONENTS MARKED 'DNP' SHOULD NOT BE POPULATED." at 1008.92,-528.5 h60
  text "ASSEMBLY VARIANT:" at 1008.42,-644 h60
  text ".VariantName" at 2044.42,-644 h60
  text "PCB VIEWED FROM TOP SIDE" at -378.5,-805.67 h60
  text "BOARD #:" at 2098,-805.67 h60
  text ".PRJ_Number" at 2643.5,-805.67 h60
  text "REV:" at 3488,-805.67 h60
  text ".PCB_Rev" at 3779.5,-805.67 h60
  text "SVN REV:" at 4326,-805.67 h60
  text ".VersionControl_RevNumber" at 4832,-805.67 h60
  text "TID #:" at 2098,-1009 h60
  text ".TID" at 2643.5,-1009 h60
  text "PLOT NAME =" at -378.5,-1214.34 h60
  text ".plot_File_Name" at 427,-1214.34 h60
  text "GENERATED    :" at 2100,-1214.34 h60
  text ".Print_Date" at 2969.5,-1214.34 h60
  text ".Print_Time" at 3698.5,-1214.34 h60
  text "TEXAS INSTRUMENTS" at 4963,-1214.34 h60
Assembly Top/Assembly Bottom Bottom:
  lines w10: -442.5,-877.33 6159.5,-877.33 ; -440.5,-1080.67 6159.5,-1080.67 ; 965.5,-1290.5 965.5,-1087.67 ; 1587.5,-877.33 1587.5,-674 ; 2427.5,-877.33 2427.5,-674 ; 3694.5,-1284 3694.5,-674 ; 4583.5,-1284 6159,-1284 6159,-674 -442.5,-674 -442.5,-1284 2154.5,-1284 6159.5,-1284 6159.5,-674
  text "COMPONENTS MARKED 'DNP' SHOULD NOT BE POPULATED." at 5952,-528 h60
  text ".VariantName" at 4908,-644 h60
  text "ASSEMBLY VARIANT:" at 5947,-644 h60
  text ".VersionControl_RevNumber" at 885.5,-806.17 h60
  text "SVN REV:" at 1391.5,-806.17 h60
  text ".PCB_Rev" at 1938,-806.17 h60
  text "REV:" at 2229.5,-806.17 h60
  text ".PRJ_Number" at 3074,-806.17 h60
  text "BOARD #:" at 3619.5,-806.17 h60
  text "PCB VIEWED FROM BOTTOM SIDE" at 6096,-806.17 h60
  text ".TID" at 3074,-1009.5 h60
  text "TID #:" at 3619.5,-1009.5 h60
  text "TEXAS INSTRUMENTS" at 754.5,-1214.84 h60
  text ".Print_Time" at 2019,-1214.84 h60
  text ".Print_Date" at 2748,-1214.84 h60
  text "GENERATED    :" at 3617.5,-1214.84 h60
  text ".plot_File_Name" at 5290.5,-1214.84 h60
  text "PLOT NAME =" at 6096,-1214.84 h60
M9 Title Sheet:
  drawing of 57 lines, arcs and shapes, not listed
  text "1" at 589.84,7886.5 h70
  text "2" at 3085.5,7886.5 h70
  text "3" at 5574.84,7886.5 h70
  text "4" at 8044.51,7886.5 h70
  text "5" at 10543.5,7886.5 h70
  text "6" at 13085.5,7886.5 h70
  text "A" at -566.5,6743.5 h70
  text "A" at 14233.5,6743.5 h70
  text "B" at -566.5,4363.5 h70
  text "B" at 14233.5,4363.5 h70
  text "C" at -566.5,1988.5 h70
  text "C" at 14233.5,1988.5 h70
  text "PROJECT TITLE:" at 11193.5,127.5 h45
  text ".PRJ_Title" at 11243.5,-5.83 h70
  text "DESIGNED FOR:" at 11193.5,-173.5 h45
  text ".PRJ_Customer" at 11243.5,-313.5 h70
  text "D" at -566.5,-381.5 h70
  text "D" at 14233.5,-381.5 h70
  text "FILE NAME:" at 11193.5,-473.5 h45
  text ".PCB_File_Name_No_Path" at 11243.5,-593.5 h70
  text "Texas Instruments (TI) and/or its licensors do not warrant the accuracy or completeness of this specification" at 6224,-755.34 h45
  text "ENGINEER:" at 11193.5,-763.5 h45
  text "LAYOUT BY:" at 12698.5,-763.5 h45
  text "or any information contained therein. TI and/or its licensors do not warrant that this design will meet" at 6179.01,-868 h45
  text ".PRJ_Engineer" at 11243.5,-918.49 h70
  text ".PCB_Layout" at 12749,-918.49 h70
  text "the specifications, will be suitable for your application or fit for any particular purpose, or will operate in" at 6179.01,-980.67 h45
  text "ALTIUM DESIGNER VERSION:" at 12698.5,-1073.5 h45
  text "an implementation. TI and/or its licensors do not warrant that the design is production worthy. You should" at 6179.01,-1093.33 h45
  text "completely validate and test your design implementation to confirm the system functionality for your application." at 6224,-1206 h45
  text ".print_Scale" at 11243.5,-1206.83 h70
  text ".Application_BuildNumber" at 12749,-1206.83 h70
  text "1" at 589.84,-1413.5 h70
  text "2" at 3085.5,-1413.5 h70
  text "3" at 5574.84,-1413.5 h70
  text "4" at 8081.51,-1413.5 h70
  text "5" at 10580.5,-1413.5 h70
  text "6" at 13085.5,-1413.5 h70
